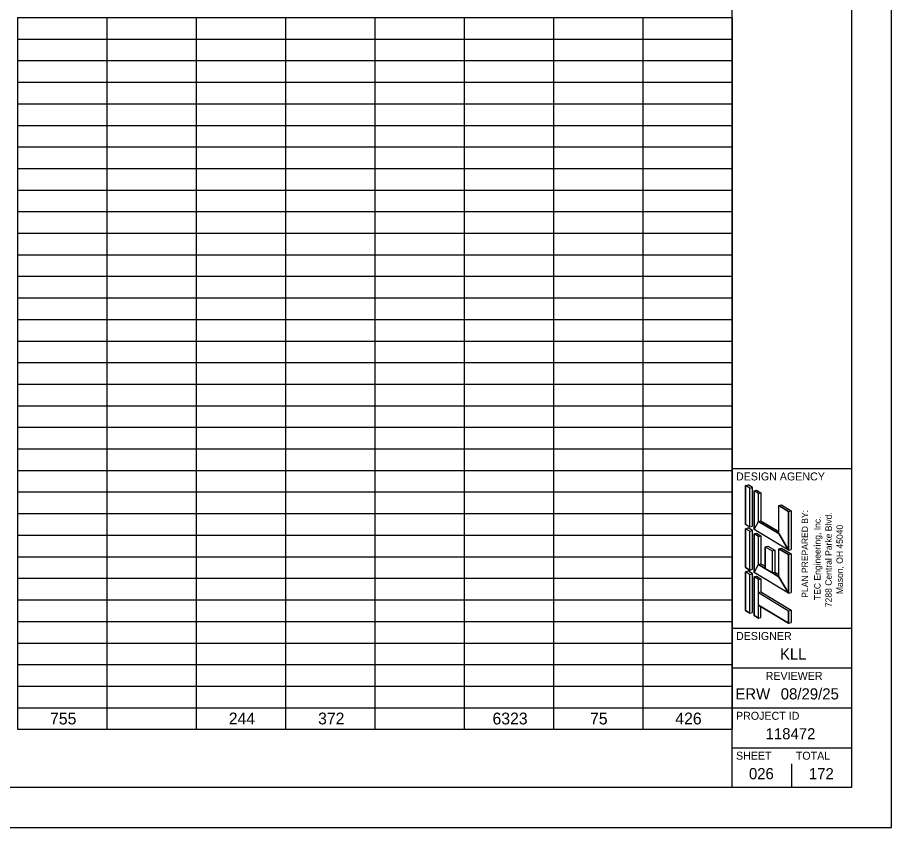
# Model space of a CAD drawing. Extents: x 0 to 34, y 0 to 22.
# Drawn here: x 23.04 to 34, y 0 to 10.15 of the extents above; entities that cross this region are included whole.
import ezdxf

# ---------------------------------------------------------------- set-up
doc = ezdxf.new("R2010")
doc.units = 0
for name, color, linetype in [('Default', 7, 'Continuous'), ('SH_Border', 7, 'Continuous'), ('SH_Cut_Line', 7, 'Continuous'), ('SH_Data', 7, 'Continuous'), ('SH_Text', 7, 'Continuous')]:
    doc.layers.add(name, color=color, linetype=linetype)

msp = doc.modelspace()

# ---------------------------------------------------------------- linework, layer by layer
at = {"layer": 'SH_Border'}
for p, q in [((32, 0.5), (32, 21.5)), ((32, 4.5), (33.5, 4.5)), ((32, 2.5), (33.5, 2.5)), ((32, 2), (33.5, 2)), ((32, 1.5), (33.5, 1.5)), ((32, 1), (33.5, 1))]:
    msp.add_line(p, q, dxfattribs=at)
msp.add_lwpolyline([(1.5, 21.5), (33.5, 21.5), (33.5, 0.5), (1.5, 0.5)], close=True, dxfattribs=at)
at = {"layer": 'SH_Cut_Line'}
msp.add_lwpolyline([(0, 0), (34, 0), (34, 22), (0, 22)], close=True, dxfattribs=at)
at = {"layer": 'SH_Data'}
for p, q in [((32.75, 3.5), (32.75, 3.5)), ((32.75, 0.5), (32.75, 0.8)), ((32.375, 0.675), (32.375, 0.675))]:
    msp.add_line(p, q, dxfattribs=at)
at = {"layer": 'SH_Text'}
for p, q in [((23.041, 10.152), (24.161, 10.152)), ((23.041, 10.152), (23.041, 9.881)), ((24.161, 10.152), (27.52, 10.152)), ((24.161, 10.152), (24.161, 9.881)), ((25.28, 10.152), (25.28, 9.881)), ((26.4, 10.152), (26.4, 9.881)), ((27.52, 10.152), (29.76, 10.152)), ((27.52, 10.152), (27.52, 9.881)), ((28.64, 10.152), (28.64, 9.881)), ((29.76, 10.152), (32, 10.152)), ((29.76, 10.152), (29.76, 9.881)), ((30.88, 10.152), (30.88, 9.881)), ((32, 10.152), (32, 9.881)), ((23.041, 9.881), (24.161, 9.881)), ((23.041, 9.881), (23.041, 9.611)), ((24.161, 9.881), (27.52, 9.881)), ((24.161, 9.881), (24.161, 9.611)), ((25.28, 9.881), (25.28, 9.611)), ((26.4, 9.881), (26.4, 9.611)), ((27.52, 9.881), (29.76, 9.881)), ((27.52, 9.881), (27.52, 9.611)), ((28.64, 9.881), (28.64, 9.611)), ((29.76, 9.881), (32, 9.881)), ((29.76, 9.881), (29.76, 9.611)), ((30.88, 9.881), (30.88, 9.611)), ((32, 9.881), (32, 9.611)), ((23.041, 9.611), (24.161, 9.611)), ((23.041, 9.611), (23.041, 9.341)), ((24.161, 9.611), (27.52, 9.611)), ((24.161, 9.611), (24.161, 9.341)), ((25.28, 9.611), (25.28, 9.341)), ((26.4, 9.611), (26.4, 9.341)), ((27.52, 9.611), (29.76, 9.611)), ((27.52, 9.611), (27.52, 9.341)), ((28.64, 9.611), (28.64, 9.341)), ((29.76, 9.611), (32, 9.611)), ((29.76, 9.611), (29.76, 9.341)), ((30.88, 9.611), (30.88, 9.341)), ((32, 9.611), (32, 9.341)), ((23.041, 9.341), (24.161, 9.341)), ((23.041, 9.341), (23.041, 9.07)), ((24.161, 9.341), (27.52, 9.341)), ((24.161, 9.341), (24.161, 9.07)), ((25.28, 9.341), (25.28, 9.07)), ((26.4, 9.341), (26.4, 9.07)), ((27.52, 9.341), (29.76, 9.341)), ((27.52, 9.341), (27.52, 9.07)), ((28.64, 9.341), (28.64, 9.07)), ((29.76, 9.341), (32, 9.341)), ((29.76, 9.341), (29.76, 9.07)), ((30.88, 9.341), (30.88, 9.07)), ((32, 9.341), (32, 9.07)), ((23.041, 9.07), (24.161, 9.07)), ((23.041, 9.07), (23.041, 8.8)), ((24.161, 9.07), (27.52, 9.07)), ((24.161, 9.07), (24.161, 8.8)), ((25.28, 9.07), (25.28, 8.8)), ((26.4, 9.07), (26.4, 8.8)), ((27.52, 9.07), (29.76, 9.07)), ((27.52, 9.07), (27.52, 8.8)), ((28.64, 9.07), (28.64, 8.8)), ((29.76, 9.07), (32, 9.07)), ((29.76, 9.07), (29.76, 8.8)), ((30.88, 9.07), (30.88, 8.8)), ((32, 9.07), (32, 8.8)), ((23.041, 8.8), (24.161, 8.8)), ((23.041, 8.8), (23.041, 8.53)), ((24.161, 8.8), (27.52, 8.8)), ((24.161, 8.8), (24.161, 8.53)), ((25.28, 8.8), (25.28, 8.53)), ((26.4, 8.8), (26.4, 8.53)), ((27.52, 8.8), (29.76, 8.8)), ((27.52, 8.8), (27.52, 8.53)), ((28.64, 8.8), (28.64, 8.53)), ((29.76, 8.8), (32, 8.8)), ((29.76, 8.8), (29.76, 8.53)), ((30.88, 8.8), (30.88, 8.53)), ((32, 8.8), (32, 8.53)), ((23.041, 8.53), (24.161, 8.53)), ((23.041, 8.53), (23.041, 8.259)), ((24.161, 8.53), (27.52, 8.53)), ((24.161, 8.53), (24.161, 8.259)), ((25.28, 8.53), (25.28, 8.259)), ((26.4, 8.53), (26.4, 8.259)), ((27.52, 8.53), (29.76, 8.53)), ((27.52, 8.53), (27.52, 8.259)), ((28.64, 8.53), (28.64, 8.259)), ((29.76, 8.53), (32, 8.53)), ((29.76, 8.53), (29.76, 8.259)), ((30.88, 8.53), (30.88, 8.259)), ((32, 8.53), (32, 8.259)), ((23.041, 8.259), (24.161, 8.259)), ((23.041, 8.259), (23.041, 7.989)), ((24.161, 8.259), (27.52, 8.259)), ((24.161, 8.259), (24.161, 7.989)), ((25.28, 8.259), (25.28, 7.989)), ((26.4, 8.259), (26.4, 7.989)), ((27.52, 8.259), (29.76, 8.259)), ((27.52, 8.259), (27.52, 7.989)), ((28.64, 8.259), (28.64, 7.989)), ((29.76, 8.259), (32, 8.259)), ((29.76, 8.259), (29.76, 7.989)), ((30.88, 8.259), (30.88, 7.989)), ((32, 8.259), (32, 7.989)), ((23.041, 7.989), (24.161, 7.989)), ((23.041, 7.989), (23.041, 7.719)), ((24.161, 7.989), (27.52, 7.989)), ((24.161, 7.989), (24.161, 7.719)), ((25.28, 7.989), (25.28, 7.719)), ((26.4, 7.989), (26.4, 7.719)), ((27.52, 7.989), (29.76, 7.989)), ((27.52, 7.989), (27.52, 7.719)), ((28.64, 7.989), (28.64, 7.719)), ((29.76, 7.989), (32, 7.989)), ((29.76, 7.989), (29.76, 7.719)), ((30.88, 7.989), (30.88, 7.719)), ((32, 7.989), (32, 7.719)), ((23.041, 7.719), (24.161, 7.719)), ((23.041, 7.719), (23.041, 7.449)), ((24.161, 7.719), (27.52, 7.719)), ((24.161, 7.719), (24.161, 7.449)), ((25.28, 7.719), (25.28, 7.449)), ((26.4, 7.719), (26.4, 7.449)), ((27.52, 7.719), (29.76, 7.719)), ((27.52, 7.719), (27.52, 7.449)), ((28.64, 7.719), (28.64, 7.449)), ((29.76, 7.719), (32, 7.719)), ((29.76, 7.719), (29.76, 7.449)), ((30.88, 7.719), (30.88, 7.449)), ((32, 7.719), (32, 7.449)), ((23.041, 7.449), (24.161, 7.449)), ((23.041, 7.449), (23.041, 7.178)), ((24.161, 7.449), (27.52, 7.449)), ((24.161, 7.449), (24.161, 7.178)), ((25.28, 7.449), (25.28, 7.178)), ((26.4, 7.449), (26.4, 7.178)), ((27.52, 7.449), (29.76, 7.449)), ((27.52, 7.449), (27.52, 7.178)), ((28.64, 7.449), (28.64, 7.178)), ((29.76, 7.449), (32, 7.449)), ((29.76, 7.449), (29.76, 7.178)), ((30.88, 7.449), (30.88, 7.178)), ((32, 7.449), (32, 7.178)), ((23.041, 7.178), (24.161, 7.178)), ((23.041, 7.178), (23.041, 6.908)), ((24.161, 7.178), (27.52, 7.178)), ((24.161, 7.178), (24.161, 6.908)), ((25.28, 7.178), (25.28, 6.908)), ((26.4, 7.178), (26.4, 6.908)), ((27.52, 7.178), (29.76, 7.178)), ((27.52, 7.178), (27.52, 6.908)), ((28.64, 7.178), (28.64, 6.908)), ((29.76, 7.178), (32, 7.178)), ((29.76, 7.178), (29.76, 6.908)), ((30.88, 7.178), (30.88, 6.908)), ((32, 7.178), (32, 6.908)), ((23.041, 6.908), (24.161, 6.908)), ((23.041, 6.908), (23.041, 6.638)), ((24.161, 6.908), (27.52, 6.908)), ((24.161, 6.908), (24.161, 6.638)), ((25.28, 6.908), (25.28, 6.638)), ((26.4, 6.908), (26.4, 6.638)), ((27.52, 6.908), (29.76, 6.908)), ((27.52, 6.908), (27.52, 6.638)), ((28.64, 6.908), (28.64, 6.638)), ((29.76, 6.908), (32, 6.908)), ((29.76, 6.908), (29.76, 6.638)), ((30.88, 6.908), (30.88, 6.638)), ((32, 6.908), (32, 6.638)), ((23.041, 6.638), (24.161, 6.638)), ((23.041, 6.638), (23.041, 6.367)), ((24.161, 6.638), (27.52, 6.638)), ((24.161, 6.638), (24.161, 6.367)), ((25.28, 6.638), (25.28, 6.367)), ((26.4, 6.638), (26.4, 6.367)), ((27.52, 6.638), (29.76, 6.638)), ((27.52, 6.638), (27.52, 6.367)), ((28.64, 6.638), (28.64, 6.367)), ((29.76, 6.638), (32, 6.638)), ((29.76, 6.638), (29.76, 6.367)), ((30.88, 6.638), (30.88, 6.367)), ((32, 6.638), (32, 6.367)), ((23.041, 6.367), (24.161, 6.367)), ((23.041, 6.367), (23.041, 6.097)), ((24.161, 6.367), (27.52, 6.367)), ((24.161, 6.367), (24.161, 6.097)), ((25.28, 6.367), (25.28, 6.097)), ((26.4, 6.367), (26.4, 6.097)), ((27.52, 6.367), (29.76, 6.367)), ((27.52, 6.367), (27.52, 6.097)), ((28.64, 6.367), (28.64, 6.097)), ((29.76, 6.367), (32, 6.367)), ((29.76, 6.367), (29.76, 6.097)), ((30.88, 6.367), (30.88, 6.097)), ((32, 6.367), (32, 6.097)), ((23.041, 6.097), (24.161, 6.097)), ((23.041, 6.097), (23.041, 5.556)), ((24.161, 6.097), (27.52, 6.097)), ((24.161, 6.097), (24.161, 5.556)), ((25.28, 6.097), (25.28, 5.556)), ((26.4, 6.097), (26.4, 5.556)), ((27.52, 6.097), (29.76, 6.097)), ((27.52, 6.097), (27.52, 5.556)), ((28.64, 6.097), (28.64, 5.556)), ((29.76, 6.097), (32, 6.097)), ((29.76, 6.097), (29.76, 5.556)), ((30.88, 6.097), (30.88, 5.556)), ((32, 6.097), (32, 5.556)), ((23.041, 5.827), (24.161, 5.827)), ((24.161, 5.827), (27.52, 5.827)), ((27.52, 5.827), (29.76, 5.827)), ((29.76, 5.827), (32, 5.827)), ((23.041, 5.556), (24.161, 5.556)), ((23.041, 5.556), (23.041, 5.286)), ((24.161, 5.556), (27.52, 5.556)), ((24.161, 5.556), (24.161, 5.286)), ((25.28, 5.556), (25.28, 5.286)), ((26.4, 5.556), (26.4, 5.286)), ((27.52, 5.556), (29.76, 5.556)), ((27.52, 5.556), (27.52, 5.286)), ((28.64, 5.556), (28.64, 5.286)), ((29.76, 5.556), (32, 5.556)), ((29.76, 5.556), (29.76, 5.286)), ((30.88, 5.556), (30.88, 5.286)), ((32, 5.556), (32, 5.286)), ((23.041, 5.286), (24.161, 5.286)), ((23.041, 5.286), (23.041, 5.016)), ((24.161, 5.286), (27.52, 5.286)), ((24.161, 5.286), (24.161, 5.016)), ((25.28, 5.286), (25.28, 5.016)), ((26.4, 5.286), (26.4, 5.016)), ((27.52, 5.286), (29.76, 5.286)), ((27.52, 5.286), (27.52, 5.016)), ((28.64, 5.286), (28.64, 5.016)), ((29.76, 5.286), (32, 5.286)), ((29.76, 5.286), (29.76, 5.016)), ((30.88, 5.286), (30.88, 5.016)), ((32, 5.286), (32, 5.016)), ((23.041, 5.016), (24.161, 5.016)), ((23.041, 5.016), (23.041, 4.745)), ((24.161, 5.016), (27.52, 5.016)), ((24.161, 5.016), (24.161, 4.745)), ((25.28, 5.016), (25.28, 4.745)), ((26.4, 5.016), (26.4, 4.745)), ((27.52, 5.016), (29.76, 5.016)), ((27.52, 5.016), (27.52, 4.745)), ((28.64, 5.016), (28.64, 4.745)), ((29.76, 5.016), (32, 5.016)), ((29.76, 5.016), (29.76, 4.745)), ((30.88, 5.016), (30.88, 4.745)), ((32, 5.016), (32, 4.745)), ((23.041, 4.745), (24.161, 4.745)), ((23.041, 4.745), (23.041, 4.205)), ((24.161, 4.745), (27.52, 4.745)), ((24.161, 4.745), (24.161, 4.205)), ((25.28, 4.745), (25.28, 4.205)), ((26.4, 4.745), (26.4, 4.205)), ((27.52, 4.745), (29.76, 4.745)), ((27.52, 4.745), (27.52, 4.205)), ((28.64, 4.745), (28.64, 4.205)), ((29.76, 4.745), (32, 4.745)), ((29.76, 4.745), (29.76, 4.205)), ((30.88, 4.745), (30.88, 4.205)), ((32, 4.745), (32, 4.205)), ((23.041, 4.475), (24.161, 4.475)), ((24.161, 4.475), (27.52, 4.475)), ((27.52, 4.475), (29.76, 4.475)), ((29.76, 4.475), (32, 4.475)), ((32.169, 4.285), (32.201, 4.294)), ((32.169, 3.799), (32.169, 4.285)), ((32.223, 4.253), (32.169, 4.285)), ((32.255, 4.261), (32.201, 4.294)), ((23.041, 4.205), (24.161, 4.205)), ((23.041, 4.205), (23.041, 3.934)), ((24.161, 4.205), (27.52, 4.205)), ((24.161, 4.205), (24.161, 3.934)), ((25.28, 4.205), (25.28, 3.934)), ((26.4, 4.205), (26.4, 3.934)), ((27.52, 4.205), (29.76, 4.205)), ((27.52, 4.205), (27.52, 3.934)), ((28.64, 4.205), (28.64, 3.934)), ((29.76, 4.205), (32, 4.205)), ((29.76, 4.205), (29.76, 3.934)), ((30.88, 4.205), (30.88, 3.934)), ((32, 4.205), (32, 3.934)), ((32.223, 4.253), (32.255, 4.261)), ((32.223, 3.767), (32.223, 4.253)), ((32.255, 3.775), (32.255, 4.261)), ((32.277, 4.221), (32.309, 4.229)), ((32.331, 4.188), (32.277, 4.221)), ((32.277, 3.735), (32.277, 4.221)), ((32.309, 4.229), (32.363, 4.196)), ((32.331, 4.188), (32.363, 4.196)), ((32.331, 3.837), (32.331, 4.188)), ((32.363, 4.196), (32.363, 3.845)), ((32.587, 4.034), (32.62, 4.042)), ((32.587, 3.683), (32.587, 4.034)), ((32.709, 3.961), (32.587, 4.034)), ((32.62, 4.042), (32.741, 3.97)), ((32.709, 3.961), (32.741, 3.97)), ((32.709, 3.475), (32.709, 3.961)), ((32.741, 3.97), (32.741, 3.484)), ((23.041, 3.934), (24.161, 3.934)), ((23.041, 3.934), (23.041, 3.664)), ((24.161, 3.934), (27.52, 3.934)), ((24.161, 3.934), (24.161, 3.664)), ((25.28, 3.934), (25.28, 3.664)), ((26.4, 3.934), (26.4, 3.664)), ((27.52, 3.934), (29.76, 3.934)), ((27.52, 3.934), (27.52, 3.664)), ((28.64, 3.934), (28.64, 3.664)), ((29.76, 3.934), (32, 3.934)), ((29.76, 3.934), (29.76, 3.664)), ((30.88, 3.934), (30.88, 3.664)), ((32, 3.934), (32, 3.664)), ((32.331, 3.837), (32.363, 3.845)), ((32.587, 3.683), (32.331, 3.837)), ((32.363, 3.845), (32.587, 3.711)), ((32.223, 3.767), (32.169, 3.799)), ((32.169, 3.745), (32.201, 3.754)), ((32.169, 3.259), (32.169, 3.745)), ((32.223, 3.713), (32.169, 3.745)), ((32.255, 3.722), (32.201, 3.754)), ((32.223, 3.767), (32.255, 3.775)), ((32.709, 3.475), (32.277, 3.735)), ((23.041, 3.664), (24.161, 3.664)), ((23.041, 3.664), (23.041, 3.394)), ((24.161, 3.664), (27.52, 3.664)), ((24.161, 3.664), (24.161, 3.394)), ((25.28, 3.664), (25.28, 3.394)), ((26.4, 3.664), (26.4, 3.394)), ((27.52, 3.664), (29.76, 3.664)), ((27.52, 3.664), (27.52, 3.394)), ((28.64, 3.664), (28.64, 3.394)), ((29.76, 3.664), (32, 3.664)), ((29.76, 3.664), (29.76, 3.394)), ((30.88, 3.664), (30.88, 3.394)), ((32, 3.664), (32, 3.394)), ((32.223, 3.713), (32.255, 3.722)), ((32.223, 3.227), (32.223, 3.713)), ((32.255, 3.236), (32.255, 3.722)), ((32.277, 3.681), (32.309, 3.689)), ((32.277, 3.195), (32.277, 3.681)), ((32.331, 3.648), (32.277, 3.681)), ((32.309, 3.689), (32.363, 3.656)), ((32.331, 3.648), (32.363, 3.656)), ((32.331, 3.297), (32.331, 3.648)), ((32.363, 3.656), (32.363, 3.305)), ((32.415, 3.519), (32.448, 3.527)), ((32.415, 3.519), (32.415, 3.247)), ((32.415, 3.519), (32.503, 3.466)), ((32.448, 3.527), (32.535, 3.474)), ((32.503, 3.466), (32.535, 3.474)), ((32.503, 3.466), (32.503, 3.194)), ((32.535, 3.474), (32.535, 3.202)), ((32.587, 3.494), (32.62, 3.502)), ((32.587, 3.143), (32.587, 3.494)), ((32.709, 3.421), (32.587, 3.494)), ((32.62, 3.502), (32.741, 3.43)), ((32.709, 3.475), (32.741, 3.484)), ((32.709, 3.421), (32.741, 3.43)), ((32.709, 2.935), (32.709, 3.421)), ((32.741, 3.43), (32.741, 2.944)), ((23.041, 3.394), (24.161, 3.394)), ((23.041, 3.394), (23.041, 2.853)), ((24.161, 3.394), (27.52, 3.394)), ((24.161, 3.394), (24.161, 2.853)), ((25.28, 3.394), (25.28, 2.853)), ((26.4, 3.394), (26.4, 2.853)), ((27.52, 3.394), (29.76, 3.394)), ((27.52, 3.394), (27.52, 2.853)), ((28.64, 3.394), (28.64, 2.853)), ((29.76, 3.394), (32, 3.394)), ((29.76, 3.394), (29.76, 2.853)), ((30.88, 3.394), (30.88, 2.853)), ((32, 3.394), (32, 2.853)), ((32.331, 3.297), (32.363, 3.305)), ((32.415, 3.247), (32.331, 3.297)), ((32.363, 3.305), (32.415, 3.274)), ((32.223, 3.227), (32.169, 3.259)), ((32.169, 3.205), (32.201, 3.215)), ((32.169, 2.719), (32.169, 3.205)), ((32.223, 3.173), (32.169, 3.205)), ((32.255, 3.181), (32.201, 3.215)), ((32.222, 3.173), (32.255, 3.181)), ((32.223, 3.227), (32.255, 3.236)), ((32.255, 2.695), (32.255, 3.181)), ((32.709, 2.935), (32.277, 3.195)), ((32.503, 3.194), (32.535, 3.202)), ((32.587, 3.143), (32.503, 3.194)), ((32.535, 3.202), (32.587, 3.171)), ((23.041, 3.123), (24.161, 3.123)), ((24.161, 3.123), (27.52, 3.123)), ((27.52, 3.123), (29.76, 3.123)), ((29.76, 3.123), (32, 3.123)), ((32.223, 2.687), (32.223, 3.173)), ((32.277, 3.141), (32.309, 3.151)), ((32.331, 3.108), (32.277, 3.141)), ((32.277, 2.655), (32.277, 3.141)), ((32.309, 3.151), (32.363, 3.116)), ((32.331, 3.108), (32.363, 3.116)), ((32.331, 2.944), (32.331, 3.108)), ((32.363, 3.116), (32.363, 2.952)), ((23.041, 2.853), (24.161, 2.853)), ((23.041, 2.853), (23.041, 2.583)), ((24.161, 2.853), (27.52, 2.853)), ((24.161, 2.853), (24.161, 2.583)), ((25.28, 2.853), (25.28, 2.583)), ((26.4, 2.853), (26.4, 2.583)), ((27.52, 2.853), (29.76, 2.853)), ((27.52, 2.853), (27.52, 2.583)), ((28.64, 2.853), (28.64, 2.583)), ((29.76, 2.853), (32, 2.853)), ((29.76, 2.853), (29.76, 2.583)), ((30.88, 2.853), (30.88, 2.583)), ((32, 2.853), (32, 2.583)), ((32.331, 2.944), (32.363, 2.952)), ((32.331, 2.944), (32.709, 2.717)), ((32.363, 2.952), (32.741, 2.725)), ((32.709, 2.935), (32.741, 2.944)), ((32.331, 2.787), (32.709, 2.56)), ((32.331, 2.622), (32.331, 2.787)), ((32.363, 2.63), (32.363, 2.767)), ((32.223, 2.687), (32.169, 2.719)), ((32.223, 2.687), (32.255, 2.695)), ((32.331, 2.622), (32.277, 2.655)), ((32.331, 2.622), (32.363, 2.63)), ((32.709, 2.717), (32.741, 2.725)), ((32.709, 2.56), (32.709, 2.717)), ((32.741, 2.725), (32.741, 2.568)), ((23.041, 2.583), (24.161, 2.583)), ((23.041, 2.583), (23.041, 2.312)), ((24.161, 2.583), (27.52, 2.583)), ((24.161, 2.583), (24.161, 2.312)), ((25.28, 2.583), (25.28, 2.312)), ((26.4, 2.583), (26.4, 2.312)), ((27.52, 2.583), (29.76, 2.583)), ((27.52, 2.583), (27.52, 2.312)), ((28.64, 2.583), (28.64, 2.312)), ((29.76, 2.583), (32, 2.583)), ((29.76, 2.583), (29.76, 2.312)), ((30.88, 2.583), (30.88, 2.312)), ((32, 2.583), (32, 2.312)), ((32.709, 2.56), (32.741, 2.568)), ((23.041, 2.312), (24.161, 2.312)), ((23.041, 2.312), (23.041, 2.042)), ((24.161, 2.312), (27.52, 2.312)), ((24.161, 2.312), (24.161, 2.042)), ((25.28, 2.312), (25.28, 2.042)), ((26.4, 2.312), (26.4, 2.042)), ((27.52, 2.312), (29.76, 2.312)), ((27.52, 2.312), (27.52, 2.042)), ((28.64, 2.312), (28.64, 2.042)), ((29.76, 2.312), (32, 2.312)), ((29.76, 2.312), (29.76, 2.042)), ((30.88, 2.312), (30.88, 2.042)), ((32, 2.312), (32, 2.042)), ((23.041, 2.042), (24.161, 2.042)), ((23.041, 2.042), (23.041, 1.501)), ((24.161, 2.042), (27.52, 2.042)), ((24.161, 2.042), (24.161, 1.501)), ((25.28, 2.042), (25.28, 1.501)), ((26.4, 2.042), (26.4, 1.501)), ((27.52, 2.042), (29.76, 2.042)), ((27.52, 2.042), (27.52, 1.501)), ((28.64, 2.042), (28.64, 1.501)), ((29.76, 2.042), (32, 2.042)), ((29.76, 2.042), (29.76, 1.501)), ((30.88, 2.042), (30.88, 1.501)), ((32, 2.042), (32, 1.501)), ((23.041, 1.772), (24.161, 1.772)), ((24.161, 1.772), (27.52, 1.772)), ((27.52, 1.772), (29.76, 1.772)), ((29.76, 1.772), (32, 1.772)), ((23.041, 1.501), (24.161, 1.501)), ((23.041, 1.501), (23.041, 1.231)), ((24.161, 1.501), (27.52, 1.501)), ((24.161, 1.501), (24.161, 1.231)), ((25.28, 1.501), (25.28, 1.231)), ((26.4, 1.501), (26.4, 1.231)), ((27.52, 1.501), (29.76, 1.501)), ((27.52, 1.501), (27.52, 1.231)), ((28.64, 1.501), (28.64, 1.231)), ((29.76, 1.501), (32, 1.501)), ((29.76, 1.501), (29.76, 1.231)), ((30.88, 1.501), (30.88, 1.231)), ((32, 1.501), (32, 1.231)), ((23.041, 1.231), (24.161, 1.231)), ((24.161, 1.231), (27.52, 1.231)), ((27.52, 1.231), (29.76, 1.231)), ((29.76, 1.231), (32, 1.231))]:
    msp.add_line(p, q, dxfattribs=at)
for points in [[(32.169, 3.799), (32.223, 3.767), (32.223, 4.253), (32.169, 4.285)], [(32.277, 3.735), (32.331, 3.837), (32.331, 4.188), (32.277, 4.221)], [(32.709, 3.475), (32.587, 3.683), (32.587, 4.034), (32.709, 3.961)], [(32.277, 3.735), (32.331, 3.837), (32.587, 3.683), (32.709, 3.475)], [(32.169, 3.259), (32.223, 3.227), (32.223, 3.713), (32.169, 3.745)], [(32.277, 3.195), (32.331, 3.297), (32.331, 3.648), (32.277, 3.681)], [(32.415, 3.247), (32.415, 3.519), (32.503, 3.466), (32.503, 3.194)], [(32.709, 2.935), (32.587, 3.143), (32.587, 3.494), (32.709, 3.421)], [(32.277, 3.195), (32.331, 3.297), (32.587, 3.143), (32.709, 2.935)], [(32.169, 2.719), (32.223, 2.687), (32.223, 3.173), (32.169, 3.205)], [(32.277, 2.655), (32.331, 2.622), (32.331, 3.108), (32.277, 3.141)], [(32.331, 2.787), (32.331, 2.944), (32.709, 2.717), (32.709, 2.56)]]:
    msp.add_lwpolyline(points, close=True, dxfattribs=at)

# ---------------------------------------------------------------- texts
at = {"layer": 'Default'}
for s, p in [('PLAN PREPARED BY:', (32.954, 2.88)), ('TEC Engineering, Inc.', (33.11, 2.851)), ('7288 Central Parke Blvd.', (33.25, 2.762)), ('Mason, OH 45040', (33.39, 2.925))]:
    msp.add_text(s, height=0.08, rotation=90, dxfattribs=at).set_placement(p)
at = {"layer": 'SH_Data'}
for s, height, p in [('DESIGN AGENCY', 0.1, (32.05, 4.35)), ('DESIGNER', 0.1, (32.05, 2.35)), ('KLL', 0.14, (32.601, 2.105)), ('REVIEWER', 0.1, (32.422, 1.85)), ('ERW', 0.14, (32.042, 1.605)), ('08/29/25', 0.14, (32.611, 1.605)), ('PROJECT ID', 0.1, (32.05, 1.35)), ('118472', 0.14, (32.421, 1.105)), ('SHEET', 0.1, (32.05, 0.85)), ('TOTAL', 0.1, (32.8, 0.85)), ('026', 0.14, (32.212, 0.605)), ('172', 0.14, (32.964, 0.605))]:
    msp.add_text(s, height=height, dxfattribs=at).set_placement(p)
at = {"layer": 'SH_Text'}
for s, p in [('755', (23.449, 1.292)), ('244', (25.69, 1.292)), ('372', (26.81, 1.292)), ('6323', (28.997, 1.292)), ('75', (30.22, 1.292)), ('426', (31.289, 1.292))]:
    msp.add_text(s, height=0.148, dxfattribs=at).set_placement(p)

doc.saveas('drawing.dxf')
